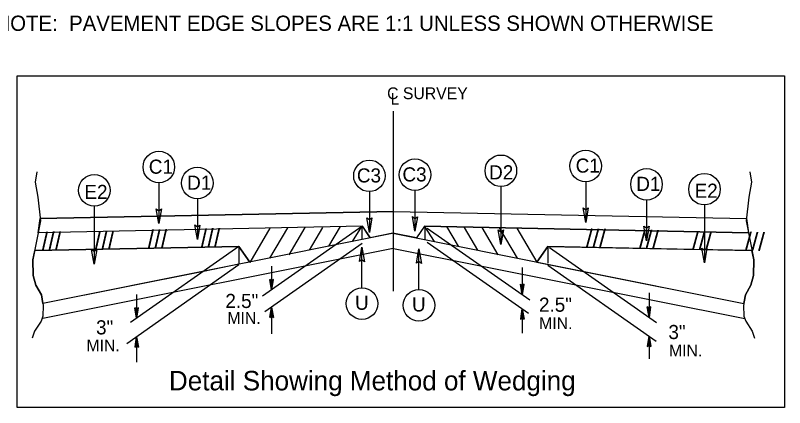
# Model space of a CAD drawing. Extents: x 2532463 to 2534146, y 189689 to 190784.
# Drawn here: x 2532655.1 to 2533010, y 190054.2 to 190235 of the extents above; entities that cross this region are included whole.
import ezdxf

# ---------------------------------------------------------------- set-up
doc = ezdxf.new("R2010")
doc.units = 0
for name, color, linetype in [('Old_Level_1', 7, 'Continuous'), ('Old_Level_10', 7, 'Continuous'), ('Old_Level_2', 7, 'Continuous'), ('Old_Level_20', 7, 'Continuous'), ('Old_Level_29', 7, 'Continuous'), ('Old_Level_30', 7, 'Continuous'), ('Old_Level_4', 7, 'Continuous')]:
    doc.layers.add(name, color=color, linetype=linetype)

msp = doc.modelspace()

# ---------------------------------------------------------------- linework, layer by layer
at = {"layer": 'Old_Level_1'}
for p, q in [((2532780.6, 190137.1), (2532772.41, 190123.03)), ((2532788.65, 190137.25), (2532781.3, 190124.65)), ((2532796.76, 190137.24), (2532790.66, 190126.8)), ((2532804.93, 190137.65), (2532799.62, 190128.55)), ((2532854.04, 190137.65), (2532859.36, 190128.55)), ((2532862.21, 190137.24), (2532868.31, 190126.8)), ((2532870.32, 190137.25), (2532877.68, 190124.65)), ((2532878.37, 190137.1), (2532886.57, 190123.03)), ((2532772.48, 190136.93), (2532763.22, 190121.07)), ((2532845.14, 190136.92), (2532892.42, 190103.8)), ((2532886.51, 190136.93), (2532895.62, 190121.3)), ((2532845.08, 190130.48), (2532891.89, 190097.7)), ((2532758.23, 190128.48), (2532664.09, 190126.59)), ((2532664.09, 190126.59), (2532758.23, 190128.48)), ((2532829.42, 190127.61), (2532667.78, 190095.28)), ((2532758.23, 190128.48), (2532708.25, 190093.48)), ((2532763.35, 190121.28), (2532758.23, 190128.48)), ((2532758.23, 190128.48), (2532758.23, 190120.27)), ((2532758.23, 190128.48), (2532763.34, 190121.3)), ((2532815.12, 190129.81), (2532770.21, 190098.37)), ((2532829.55, 190127.61), (2532991.57, 190095.2)), ((2532900.74, 190128.48), (2532895.62, 190121.3)), ((2532895.63, 190121.3), (2532900.74, 190128.48)), ((2532900.74, 190128.48), (2532994.89, 190126.59)), ((2532900.74, 190128.48), (2532900.74, 190120.85)), ((2532967.88, 190127.13), (2532900.74, 190128.48)), ((2532901.5, 190127.95), (2532950.8, 190093.42)), ((2532994.89, 190126.59), (2532967.88, 190127.13)), ((2532758.19, 190120.01), (2532706.52, 190083.64)), ((2532758.23, 190120.28), (2532741.84, 190117)), ((2532763.34, 190121.3), (2532758.23, 190120.28)), ((2532773.3, 190119.37), (2532773.3, 190108.46)), ((2532895.62, 190121.3), (2532917.14, 190117)), ((2532900.74, 190119.85), (2532950.72, 190084.84)), ((2532741.84, 190117), (2532667.83, 190102.19)), ((2532888.97, 190118.74), (2532888.97, 190106.23)), ((2532917.14, 190117), (2532991.15, 190102.19)), ((2532773.3, 190108.46), (2532772.45, 190113.24)), ((2532773.3, 190112.62), (2532772.45, 190113.24)), ((2532773.3, 190108.46), (2532772.57, 190113.15)), ((2532772.69, 190113.06), (2532773.3, 190108.46)), ((2532773.3, 190108.46), (2532772.81, 190112.98)), ((2532772.94, 190112.89), (2532773.3, 190108.46)), ((2532773.3, 190108.46), (2532773.06, 190112.8)), ((2532773.18, 190112.71), (2532773.3, 190108.46)), ((2532773.3, 190108.46), (2532774.15, 190113.24)), ((2532774.15, 190113.24), (2532773.3, 190112.62)), ((2532774.03, 190113.15), (2532773.3, 190108.46)), ((2532773.3, 190108.46), (2532773.9, 190113.06)), ((2532773.78, 190112.98), (2532773.3, 190108.46)), ((2532773.3, 190108.46), (2532773.66, 190112.89)), ((2532773.54, 190112.8), (2532773.3, 190108.46)), ((2532773.3, 190108.46), (2532773.42, 190112.71)), ((2532773.3, 190112.62), (2532773.3, 190108.46)), ((2532888.97, 190106.23), (2532888.12, 190111.02)), ((2532888.97, 190110.4), (2532888.12, 190111.02)), ((2532888.97, 190106.23), (2532888.24, 190110.93)), ((2532888.36, 190110.84), (2532888.97, 190106.23)), ((2532888.97, 190106.23), (2532888.48, 190110.75)), ((2532888.6, 190110.66), (2532888.97, 190106.23)), ((2532888.97, 190106.23), (2532888.72, 190110.58)), ((2532888.84, 190110.49), (2532888.97, 190106.23)), ((2532888.97, 190106.23), (2532889.81, 190111.02)), ((2532889.81, 190111.02), (2532888.97, 190110.4)), ((2532889.69, 190110.93), (2532888.97, 190106.23)), ((2532888.97, 190106.23), (2532889.57, 190110.84)), ((2532889.45, 190110.75), (2532888.97, 190106.23)), ((2532888.97, 190106.23), (2532889.33, 190110.66)), ((2532889.21, 190110.58), (2532888.97, 190106.23)), ((2532888.97, 190106.23), (2532889.09, 190110.49)), ((2532888.97, 190110.4), (2532888.97, 190106.23)), ((2532711.06, 190106.33), (2532711.06, 190095.44)), ((2532947.41, 190107.12), (2532947.41, 190095.8)), ((2532711.06, 190095.44), (2532710.21, 190100.23)), ((2532711.06, 190099.61), (2532710.21, 190100.23)), ((2532711.06, 190095.44), (2532710.33, 190100.15)), ((2532710.46, 190100.05), (2532711.06, 190095.44)), ((2532711.06, 190095.44), (2532710.58, 190099.97)), ((2532710.7, 190099.88), (2532711.06, 190095.44)), ((2532711.06, 190095.44), (2532710.82, 190099.79)), ((2532710.94, 190099.7), (2532711.06, 190095.44)), ((2532711.06, 190095.44), (2532711.91, 190100.23)), ((2532711.91, 190100.23), (2532711.06, 190099.61)), ((2532711.79, 190100.15), (2532711.06, 190095.44)), ((2532711.06, 190095.44), (2532711.67, 190100.05)), ((2532711.55, 190099.97), (2532711.06, 190095.44)), ((2532711.06, 190095.44), (2532711.42, 190099.88)), ((2532711.31, 190099.79), (2532711.06, 190095.44)), ((2532711.06, 190095.44), (2532711.18, 190099.7)), ((2532711.06, 190099.61), (2532711.06, 190095.44)), ((2532773.3, 190100.53), (2532772.45, 190095.74)), ((2532772.57, 190095.84), (2532773.3, 190100.53)), ((2532773.3, 190100.53), (2532772.69, 190095.92)), ((2532772.81, 190096.01), (2532773.3, 190100.53)), ((2532773.3, 190100.53), (2532772.94, 190096.1)), ((2532773.06, 190096.18), (2532773.3, 190100.53)), ((2532773.3, 190100.53), (2532773.18, 190096.27)), ((2532773.3, 190100.53), (2532773.3, 190088.24)), ((2532773.3, 190100.53), (2532774.15, 190095.74)), ((2532773.3, 190096.36), (2532773.3, 190100.53)), ((2532773.42, 190096.27), (2532773.3, 190100.53)), ((2532773.3, 190100.53), (2532773.54, 190096.18)), ((2532773.66, 190096.1), (2532773.3, 190100.53)), ((2532773.3, 190100.53), (2532773.78, 190096.01)), ((2532773.9, 190095.92), (2532773.3, 190100.53)), ((2532773.3, 190100.53), (2532774.03, 190095.84)), ((2532888.97, 190099.75), (2532888.12, 190094.96)), ((2532888.24, 190095.06), (2532888.97, 190099.75)), ((2532888.97, 190099.75), (2532888.36, 190095.14)), ((2532888.48, 190095.24), (2532888.97, 190099.75)), ((2532888.97, 190099.75), (2532888.6, 190095.32)), ((2532888.72, 190095.4), (2532888.97, 190099.75)), ((2532888.97, 190099.75), (2532888.84, 190095.49)), ((2532888.97, 190099.75), (2532888.97, 190088.55)), ((2532888.97, 190099.75), (2532889.81, 190094.96)), ((2532888.97, 190095.58), (2532888.97, 190099.75)), ((2532889.09, 190095.49), (2532888.97, 190099.75)), ((2532888.97, 190099.75), (2532889.21, 190095.4)), ((2532889.33, 190095.32), (2532888.97, 190099.75)), ((2532888.97, 190099.75), (2532889.45, 190095.24)), ((2532889.57, 190095.14), (2532888.97, 190099.75)), ((2532888.97, 190099.75), (2532889.69, 190095.06)), ((2532947.41, 190095.8), (2532946.57, 190100.58)), ((2532947.41, 190099.97), (2532946.57, 190100.58)), ((2532947.41, 190095.8), (2532946.69, 190100.49)), ((2532946.81, 190100.41), (2532947.41, 190095.8)), ((2532947.41, 190095.8), (2532946.93, 190100.33)), ((2532947.05, 190100.23), (2532947.41, 190095.8)), ((2532947.41, 190095.8), (2532947.17, 190100.15)), ((2532947.29, 190100.05), (2532947.41, 190095.8)), ((2532947.41, 190095.8), (2532948.26, 190100.58)), ((2532948.26, 190100.58), (2532947.41, 190099.97)), ((2532948.13, 190100.49), (2532947.41, 190095.8)), ((2532947.41, 190095.8), (2532948.01, 190100.41)), ((2532947.89, 190100.33), (2532947.41, 190095.8)), ((2532947.41, 190095.8), (2532947.77, 190100.23)), ((2532947.65, 190100.15), (2532947.41, 190095.8)), ((2532947.41, 190095.8), (2532947.53, 190100.05)), ((2532947.41, 190099.97), (2532947.41, 190095.8)), ((2532772.45, 190095.74), (2532773.3, 190096.36)), ((2532773.3, 190096.36), (2532774.15, 190095.74)), ((2532888.12, 190094.96), (2532888.97, 190095.58)), ((2532888.97, 190095.58), (2532889.81, 190094.96)), ((2532711.06, 190086.83), (2532710.21, 190082.04)), ((2532710.34, 190082.13), (2532711.06, 190086.83)), ((2532711.06, 190086.83), (2532710.46, 190082.22)), ((2532710.58, 190082.31), (2532711.06, 190086.83)), ((2532711.06, 190086.83), (2532710.7, 190082.4)), ((2532710.82, 190082.48), (2532711.06, 190086.83)), ((2532711.06, 190086.83), (2532710.94, 190082.57)), ((2532711.06, 190086.83), (2532711.06, 190075.19)), ((2532711.06, 190086.83), (2532711.91, 190082.04)), ((2532711.06, 190082.66), (2532711.06, 190086.83)), ((2532711.18, 190082.57), (2532711.06, 190086.83)), ((2532711.06, 190086.83), (2532711.31, 190082.48)), ((2532711.43, 190082.4), (2532711.06, 190086.83)), ((2532711.06, 190086.83), (2532711.55, 190082.31)), ((2532711.67, 190082.22), (2532711.06, 190086.83)), ((2532711.06, 190086.83), (2532711.79, 190082.13)), ((2532947.41, 190087.16), (2532946.57, 190082.37)), ((2532946.69, 190082.46), (2532947.41, 190087.16)), ((2532947.41, 190087.16), (2532946.81, 190082.55)), ((2532946.93, 190082.64), (2532947.41, 190087.16)), ((2532947.41, 190087.16), (2532947.05, 190082.73)), ((2532947.17, 190082.82), (2532947.41, 190087.16)), ((2532947.41, 190087.16), (2532947.29, 190082.91)), ((2532947.41, 190087.16), (2532947.41, 190076.65)), ((2532947.41, 190087.16), (2532948.26, 190082.37)), ((2532947.41, 190083), (2532947.41, 190087.16)), ((2532947.53, 190082.91), (2532947.41, 190087.16)), ((2532947.41, 190087.16), (2532947.65, 190082.82)), ((2532947.77, 190082.73), (2532947.41, 190087.16)), ((2532947.41, 190087.16), (2532947.89, 190082.64)), ((2532948.01, 190082.55), (2532947.41, 190087.16)), ((2532947.41, 190087.16), (2532948.13, 190082.46)), ((2532710.21, 190082.04), (2532711.06, 190082.66)), ((2532711.06, 190082.66), (2532711.91, 190082.04)), ((2532946.57, 190082.37), (2532947.41, 190083)), ((2532947.41, 190083), (2532948.26, 190082.37))]:
    msp.add_line(p, q, dxfattribs=at)
at = {"layer": 'Old_Level_10'}
for points in [[(2532665.09, 190162.84), (2532664.22, 190158.07), (2532665.53, 190151.28), (2532666.68, 190140.3), (2532665.09, 190131.63), (2532663.22, 190122.24), (2532663.36, 190115.16), (2532664.52, 190110.69), (2532667.12, 190106.2), (2532667.99, 190101.29), (2532667.84, 190096.38), (2532666.97, 190094.06), (2532663.94, 190089.44), (2532662.93, 190086.26)], [(2532993.88, 190162.84), (2532994.75, 190158.07), (2532993.45, 190151.28), (2532992.29, 190140.3), (2532993.88, 190131.63), (2532995.76, 190122.24), (2532995.62, 190115.16), (2532994.45, 190110.69), (2532991.86, 190106.2), (2532990.99, 190101.29), (2532991.13, 190096.38), (2532992, 190094.06), (2532995.03, 190089.44), (2532996.04, 190086.26)], [(2532667.82, 190102.19), (2532667.12, 190106.2), (2532664.52, 190110.69), (2532663.36, 190115.16), (2532663.22, 190122.24), (2532664.09, 190126.59)], [(2532991.15, 190102.19), (2532991.86, 190106.2), (2532994.45, 190110.69), (2532995.62, 190115.16), (2532995.76, 190122.24), (2532994.89, 190126.59)]]:
    msp.add_lwpolyline(points, dxfattribs=at)
at = {"layer": 'Old_Level_2'}
msp.add_lwpolyline([(2532655.97, 190207.09), (2533009.96, 190207.09), (2533009.96, 190054.18), (2532655.97, 190054.18)], close=True, dxfattribs=at)
at = {"layer": 'Old_Level_20'}
for p, q in [((2532829.49, 190107.93), (2532829.49, 190190.92)), ((2532829.49, 190107.93), (2532829.49, 190164.61)), ((2532918.22, 190158.33), (2532918.22, 190139.52)), ((2532721.32, 190157.82), (2532721.32, 190139.02)), ((2532879.09, 190156.1), (2532879.09, 190129.36)), ((2532818.46, 190153.77), (2532818.46, 190134.97)), ((2532839.47, 190154.27), (2532839.47, 190135.46)), ((2532739.1, 190150.43), (2532739.1, 190131.63)), ((2532946.26, 190149.89), (2532946.26, 190131.09)), ((2532829.48, 190144.59), (2532666.61, 190141.34)), ((2532666.61, 190141.34), (2532829.48, 190144.59)), ((2532691.52, 190147.07), (2532691.52, 190120.34)), ((2532829.48, 190144.59), (2532992.37, 190141.34)), ((2532829.5, 190144.59), (2532992.37, 190141.34)), ((2532972.99, 190147.62), (2532972.99, 190120.88)), ((2532665.68, 190134.8), (2532666.61, 190141.34)), ((2532992.37, 190141.34), (2532993.3, 190134.8)), ((2532815.2, 190137.79), (2532665.68, 190134.8)), ((2532815.2, 190137.79), (2532665.68, 190134.8)), ((2532815.01, 190137.67), (2532769.12, 190105.52)), ((2532810.57, 190130.82), (2532814.99, 190137.73)), ((2532814.99, 190137.73), (2532814.99, 190132.05)), ((2532818.85, 190132.42), (2532815.2, 190137.79)), ((2532815.2, 190137.61), (2532818.85, 190132.42)), ((2532843.9, 190137.79), (2532840.12, 190132.42)), ((2532843.9, 190137.79), (2532840.12, 190132.42)), ((2532843.66, 190137.67), (2532843.89, 190137.65)), ((2532843.9, 190137.79), (2532993.3, 190134.8)), ((2532993.3, 190134.8), (2532843.9, 190137.79)), ((2532848.41, 190130.82), (2532843.99, 190137.73)), ((2532843.99, 190137.73), (2532843.99, 190131.47)), ((2532829.73, 190134.58), (2532667.83, 190102.19)), ((2532829.24, 190134.58), (2532818.85, 190132.42)), ((2532829.24, 190134.58), (2532991.15, 190102.19)), ((2532840.12, 190132.42), (2532829.24, 190134.58)), ((2532814.99, 190109.42), (2532814.99, 190128.22)), ((2532841.27, 190108.65), (2532841.27, 190127.45))]:
    msp.add_line(p, q, dxfattribs=at)
for points in [[(2532722.48, 190145.76), (2532721.32, 190139.02), (2532720.12, 190145.79), (2532721.32, 190144.93)], [(2532919.38, 190146.26), (2532918.22, 190139.52), (2532917.03, 190146.3), (2532918.22, 190145.44)], [(2532819.62, 190141.71), (2532818.46, 190134.97), (2532817.26, 190141.75), (2532818.46, 190140.88)], [(2532840.63, 190142.2), (2532839.47, 190135.46), (2532838.27, 190142.24), (2532839.47, 190141.38)], [(2532740.26, 190138.37), (2532739.1, 190131.63), (2532737.91, 190138.4), (2532739.1, 190137.54)], [(2532947.42, 190137.82), (2532946.26, 190131.09), (2532945.06, 190137.86), (2532946.26, 190137)], [(2532880.25, 190136.1), (2532879.09, 190129.36), (2532877.89, 190136.14), (2532879.09, 190135.28)], [(2532692.68, 190127.07), (2532691.52, 190120.34), (2532690.32, 190127.11), (2532691.52, 190126.25)], [(2532813.83, 190121.49), (2532814.99, 190128.22), (2532816.19, 190121.45), (2532814.99, 190122.31)], [(2532840.11, 190120.71), (2532841.27, 190127.45), (2532842.47, 190120.68), (2532841.27, 190121.54)], [(2532974.15, 190127.62), (2532972.99, 190120.88), (2532971.79, 190127.65), (2532972.99, 190126.79)]]:
    msp.add_lwpolyline(points, close=True, dxfattribs=at)
for centre in [(2532918.22, 190165.6), (2532721.32, 190165.09), (2532879.08, 190163.37), (2532818.46, 190161.05), (2532839.47, 190161.54), (2532739.1, 190157.71), (2532946.26, 190157.16), (2532972.99, 190154.89), (2532691.51, 190154.34), (2532814.99, 190102.15), (2532841.27, 190101.37)]:
    msp.add_circle(centre, 7.28, dxfattribs=at)

# ---------------------------------------------------------------- texts
at = {"layer": 'Old_Level_10'}
for s, height, p in [('C SURVEY ', 5.441, (2532826.61, 190196.4)), ('L', 5.44, (2532828.2, 190193.86))]:
    msp.add_text(s, height=height, dxfattribs=at).set_placement(p)
for height, rotation, p in [(8.165, 1.1463, (2532740.7, 190128.22)), (8.168, 1.1447, (2532667.33, 190126.71)), (8.168, 1.1464, (2532691.74, 190127)), (8.165, 1.1445, (2532716.21, 190127.71)), (8.165, 358.8553, (2532918.28, 190128.22)), (8.165, 358.8536, (2532942.77, 190127.71)), (8.168, 358.8554, (2532967.23, 190127)), (8.168, 358.8537, (2532991.64, 190126.71))]:
    msp.add_text('/// ', height=height, rotation=rotation, dxfattribs=at).set_placement(p)
at = {"layer": 'Old_Level_29'}
for s, height, p in [('C1', 6.512, (2532913.59, 190162.52)), ('C1', 6.512, (2532716.68, 190162.02)), ('D2', 6.512, (2532873.67, 190159.41)), ('C3', 6.512, (2532812.67, 190157.98)), ('C3', 6.512, (2532833.68, 190158.46)), ('D1', 6.512, (2532734.38, 190154.63)), ('D1', 6.512, (2532941.54, 190154.09)), ('E2', 6.512, (2532686.98, 190150.38)), ('E2', 6.512, (2532968.45, 190150.93)), ('2.5" ', 6.512, (2532751.99, 190100.11)), ('U', 6.51, (2532811.81, 190099.27)), ('U', 6.51, (2532838.09, 190098.49)), ('2.5" ', 6.512, (2532896.66, 190098.39)), ('3" ', 6.512, (2532692.35, 190087.93)), (' 3" ', 6.512, (2532953.94, 190085.78))]:
    msp.add_text(s, height=height, dxfattribs=at).set_placement(p)
at = {"layer": 'Old_Level_30'}
for s, height, p in [('MIN.', 5.441, (2532752.93, 190092.75)), ('MIN.', 5.441, (2532896.74, 190090.39)), ('MIN.', 5.441, (2532687.92, 190080.14)), ('MIN.', 5.441, (2532956.63, 190077.77)), ('Detail Showing Method of Wedging', 8.9818, (2532725.97, 190062.12))]:
    msp.add_text(s, height=height, dxfattribs=at).set_placement(p)
at = {"layer": 'Old_Level_4'}
msp.add_text('NOTE:  PAVEMENT EDGE SLOPES ARE 1:1 UNLESS SHOWN OTHERWISE', height=7.0312, rotation=0.0001, dxfattribs=at).set_placement((2532645.95, 190227.89))

doc.saveas('drawing.dxf')
